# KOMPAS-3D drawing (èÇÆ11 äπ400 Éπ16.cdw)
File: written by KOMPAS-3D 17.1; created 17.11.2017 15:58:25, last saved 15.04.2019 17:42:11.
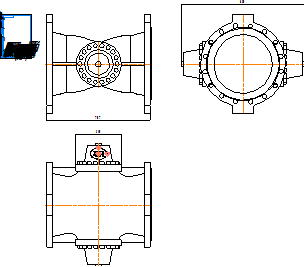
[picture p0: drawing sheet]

Sheet 1: A4, portrait

Title block, sheet 1: name: КАТ11 Ду400 Ру16; material: Внимание! Данный продукт является объектом авторского права ООО «Торговый Дом АДЛ». / Запрещается изменение, копирование, распространение / (в том числе путем копирования на другие сайты и ресурсы в Интернете) / или любое иное использование информации и объектов без предварительного / согласия правообладателя (ООО «Торговый Дом АДЛ»).; mass: 12,4; sheets: 1; organisation: ООО "Торговый дом АДЛ"; sheet format: A4; stored path: \\adlc.lan\data\АДЛ_ПКД\3D-модели\ADL production\Клапаны КАТ ГРАНРЕГ\КАТ11\KOMPAS 2D\КАТ11 Ду400 Ру16.cdw

Views: Вид 1, Проекционный вид 2, Проекционный вид 3
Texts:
  kka
  adl
Dimensions and other numbers on the sheet: 707; 830; 310; 1:1; 1; 12,4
